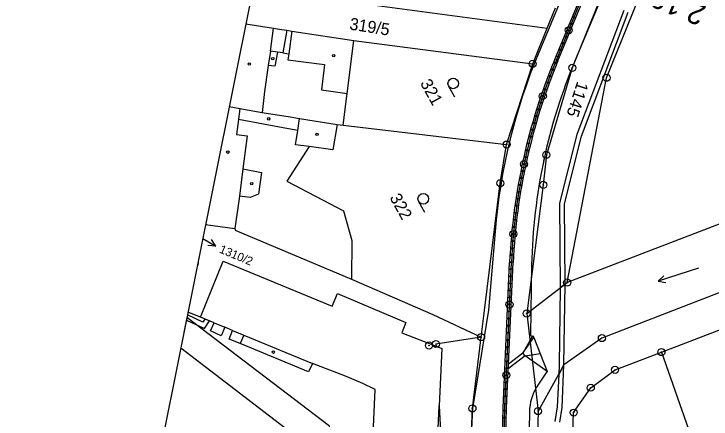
# Model space of a CAD drawing. Extents: x -548552 to -543113, y -1131925 to -1123599.
# Drawn here: x -548071.3 to -547972.8, y -1129654 to -1129596.7 of the extents above; entities that cross this region are included whole.
import ezdxf

# ---------------------------------------------------------------- set-up
doc = ezdxf.new("R2010")
doc.units = 0
for name, color, linetype in [('Hranice parcel', 7, 'Continuous'), ('HRANY', 7, 'Continuous'), ('Parcelní čísla', 7, 'Continuous'), ('Pop  PČ popisy', 7, 'Continuous'), ('Profile', 7, 'Continuous'), ('PROFILY NÁVRH', 7, 'Continuous'), ('STANIČENÍ', 7, 'Continuous'), ('Vnitřní kresba', 7, 'Continuous'), ('Věcná břemena k části', 7, 'Continuous'), ('Značky bodu BP', 7, 'Continuous'), ('Značky budov', 7, 'Continuous'), ('Značky kultur', 7, 'Continuous')]:
    doc.layers.add(name, color=color, linetype=linetype)

msp = doc.modelspace()

# ---------------------------------------------------------------- linework, layer by layer
at = {"layer": 'Hranice parcel'}
for p, q in [((-548037.579, -1129593.153), (-547995.97, -1129598.702)), ((-547995.97, -1129598.702), (-547994.817, -1129595.855)), ((-547998.02, -1129603.764), (-547995.97, -1129598.702)), ((-548023.301, -1129600.485), (-547998.02, -1129603.764)), ((-548001.707, -1129615.191), (-547998.02, -1129603.764)), ((-548025.671, -1129612.347), (-548024.825, -1129612.449)), ((-548024.825, -1129612.449), (-548001.707, -1129615.191)), ((-547998.869, -1129639.088), (-547993.145, -1129634.708)), ((-547998.869, -1129639.088), (-547997.264, -1129652.895)), ((-547979.823, -1129644.548), (-547953.676, -1129719.362)), ((-548012.947, -1129688.529), (-548011.248, -1129652.162))]:
    msp.add_line(p, q, dxfattribs=at)
for points in [[(-547943.94, -1129449.598), (-547944.146, -1129450.509), (-547954.87, -1129503.19), (-547960.132, -1129522.674), (-547965.208, -1129537.16), (-547992.427, -1129604.341), (-547996.089, -1129616.635), (-547996.527, -1129620.893), (-547998.869, -1129639.088)], [(-547993.145, -1129634.708), (-547987.59, -1129605.739), (-547960.434, -1129538.672), (-547955.317, -1129523.992), (-547949.866, -1129504.003), (-547942.366, -1129467.124)], [(-548038.577, -1129598.13), (-548034.635, -1129598.737), (-548033.531, -1129598.913), (-548032.796, -1129599.02), (-548032.057, -1129599.136), (-548023.301, -1129600.485)], [(-547897.642, -1129598.01), (-547902.313, -1129599.815), (-547935.147, -1129612.431), (-547948.722, -1129617.647), (-547993.145, -1129634.708)], [(-548024.825, -1129612.449), (-548024.231, -1129607.956), (-548023.301, -1129600.485)], [(-547888.295, -1129603.978), (-547898.682, -1129608.002), (-547945.124, -1129625.898), (-547988.244, -1129642.567), (-547993.598, -1129646.375), (-547997.264, -1129652.895)], [(-548040.919, -1129609.815), (-548039.435, -1129610.073), (-548036.242, -1129610.633), (-548032.28, -1129611.258), (-548030.977, -1129611.484), (-548025.671, -1129612.347)], [(-547979.823, -1129644.548), (-547943.108, -1129630.475), (-547896.786, -1129612.714), (-547895.105, -1129612.055)], [(-548025.671, -1129612.347), (-548026.277, -1129615.932), (-548029.609, -1129615.471), (-548032.764, -1129620.357), (-548024.77, -1129624.577), (-548023.568, -1129628.76), (-548023.654, -1129634.229)], [(-548005.313, -1129642.437), (-548004.835, -1129638.683), (-548002.599, -1129620.65), (-548001.707, -1129615.191)], [(-548044.262, -1129626.495), (-548040.119, -1129627.072), (-548040.087, -1129627.295), (-548023.654, -1129634.229)], [(-548045.235, -1129631.346), (-548045.372, -1129632.3), (-548045.424, -1129632.292)], [(-548023.654, -1129634.229), (-548012.121, -1129639.24), (-548005.313, -1129642.437)], [(-548020.334, -1129688.513), (-548021.556, -1129678.36), (-548020.302, -1129649.823), (-548022.053, -1129648.976), (-548024.478, -1129647.967), (-548029.122, -1129646.176), (-548029.703, -1129647.333), (-548039.361, -1129643.351), (-548040.933, -1129642.703), (-548040.434, -1129641.5), (-548041.546, -1129641.042), (-548042.036, -1129642.24), (-548043.561, -1129641.554), (-548043.064, -1129640.409), (-548044.987, -1129639.624), (-548046.749, -1129638.9)], [(-548019.133, -1129730.431), (-548011.696, -1129717.437), (-548008.935, -1129707.702), (-548006.542, -1129652.522), (-548005.313, -1129642.437)], [(-548005.313, -1129642.437), (-548011.703, -1129643.412), (-548011.685, -1129643.734), (-548010.865, -1129644.056), (-548011.248, -1129652.162)], [(-547994.011, -1129717.728), (-547992.884, -1129672.298), (-547992.237, -1129653.112), (-547989.811, -1129649.591), (-547986.388, -1129647.062), (-547979.823, -1129644.548)], [(-548011.248, -1129652.162), (-548009.853, -1129678.301), (-548009.88, -1129688.553), (-548012.947, -1129688.529)], [(-547997.264, -1129652.895), (-547997.82, -1129672.225), (-548001.102, -1129719.069), (-548002.902, -1129722.665), (-548006.626, -1129729.286)]]:
    msp.add_lwpolyline(points, dxfattribs=at)
at = {"layer": 'HRANY'}
msp.add_line((-547998.054, -1129642.265), (-547997.84, -1129642.499), dxfattribs=at)
at = {"layer": 'Pop  PČ popisy'}
for p, q in [((-548044.661, -1129628.487), (-548042.821, -1129629.547)), ((-548042.821, -1129629.547), (-548043.439, -1129628.614)), ((-548042.821, -1129629.547), (-548043.938, -1129629.482))]:
    msp.add_line(p, q, dxfattribs=at)
at = {"layer": 'Profile'}
for p, q in [((-548006.813, -1129439.666), (-548048.236, -1129646.318)), ((-548025.127, -1129531.035), (-548048.236, -1129646.318)), ((-548048.236, -1129646.318), (-548071.344, -1129761.602)), ((-548048.236, -1129646.318), (-548071.344, -1129761.602))]:
    msp.add_line(p, q, dxfattribs=at)
at = {"layer": 'PROFILY NÁVRH'}
for p, q in [((-547986.028, -1129575.53), (-547997.159, -1129602.147)), ((-547994.909, -1129603.145), (-547984.09, -1129576.932)), ((-547994.447, -1129603.336), (-547983.628, -1129577.123)), ((-547981.182, -1129577.47), (-547992.009, -1129603.233)), ((-548003.347, -1129627.479), (-548004.275, -1129638.622)), ((-548002.218, -1129652.424), (-548001.283, -1129631.859)), ((-548001.719, -1129652.447), (-548000.784, -1129631.882)), ((-547998.176, -1129632.222), (-547998.319, -1129642.096)), ((-548004.275, -1129638.622), (-548006.542, -1129652.522)), ((-547998.054, -1129642.265), (-547999.399, -1129644.68)), ((-547999.399, -1129644.68), (-547997.84, -1129642.499)), ((-547997.84, -1129642.499), (-547995.955, -1129647.282)), ((-547999.399, -1129644.68), (-548001.438, -1129646.275)), ((-547999.091, -1129645.074), (-547999.399, -1129644.68)), ((-547999.091, -1129645.074), (-547996.961, -1129644.73)), ((-547999.091, -1129645.074), (-548001.468, -1129646.933)), ((-547995.955, -1129647.282), (-547999.091, -1129645.074)), ((-548006.542, -1129652.522), (-548007.989, -1129685.887)), ((-548002.94, -1129686.397), (-548002.218, -1129652.43)), ((-548002.44, -1129686.407), (-548001.718, -1129652.441)), ((-547998.484, -1129653.519), (-547999.352, -1129686.07)), ((-547998.476, -1129652.972), (-547998.484, -1129653.519))]:
    msp.add_line(p, q, dxfattribs=at)
for centre, radius, start, end in [((-547919.998, -1129634.416), 83.637, 157.30515, 175.242), ((-547919.013, -1129633.909), 79.18, 157.2059, 178.7795), ((-547998.135, -1129642.099), 0.185, 179.17207, 295.86308), ((-547974.074, -1129663.851), 27.447, 142.86479, 148.4609), ((-547991.639, -1129653.071), 6.838, 148.4609, 179.17207)]:
    msp.add_arc(centre, radius, start, end, dxfattribs=at)
for major_axis, ratio in [((-22.444, -82.346), 0.999015), ((-22.313, -81.863), 0.999009)]:
    msp.add_ellipse((-547916.1, -1129635.695), major_axis=major_axis, ratio=ratio, start_param=4.586928, end_param=4.933273, dxfattribs=at)
at = {"layer": 'STANIČENÍ'}
for p, q in [((-547994.678, -1129603.241), (-547983.859, -1129577.028)), ((-548001.968, -1129652.436), (-548001.033, -1129631.87)), ((-548002.69, -1129686.402), (-548001.968, -1129652.436))]:
    msp.add_line(p, q, dxfattribs=at)
for centre, radius in [((-547992.174, -1129597.173), 0.1), ((-547992.556, -1129598.098), 0.1), ((-547992.937, -1129599.022), 0.5), ((-547992.937, -1129599.022), 0.1), ((-547993.319, -1129599.947), 0.1), ((-547993.7, -1129600.871), 0.1), ((-547994.082, -1129601.795), 0.1), ((-547994.463, -1129602.72), 0.1), ((-547994.844, -1129603.644), 0.1), ((-547995.215, -1129604.573), 0.1), ((-547995.925, -1129606.443), 0.1), ((-547995.576, -1129605.506), 0.1), ((-547996.263, -1129607.384), 0.1), ((-547996.591, -1129608.328), 0.5), ((-547996.591, -1129608.328), 0.1), ((-547996.907, -1129609.277), 0.1), ((-547997.212, -1129610.229), 0.1), ((-547997.506, -1129611.185), 0.1), ((-547997.788, -1129612.145), 0.1), ((-547998.06, -1129613.107), 0.1), ((-547998.32, -1129614.073), 0.1), ((-547998.569, -1129615.041), 0.1), ((-547998.806, -1129616.013), 0.1), ((-547999.032, -1129616.987), 0.1), ((-547999.246, -1129617.964), 0.5), ((-547999.246, -1129617.964), 0.1), ((-547999.449, -1129618.943), 0.1), ((-547999.64, -1129619.924), 0.1), ((-547999.82, -1129620.908), 0.1), ((-547999.989, -1129621.894), 0.1), ((-548000.145, -1129622.881), 0.1), ((-548000.291, -1129623.871), 0.1), ((-548000.424, -1129624.862), 0.1), ((-548000.546, -1129625.854), 0.1), ((-548000.656, -1129626.848), 0.1), ((-548000.755, -1129627.843), 0.5), ((-548000.755, -1129627.843), 0.1), ((-548000.841, -1129628.839), 0.1), ((-548000.917, -1129629.836), 0.1), ((-548000.98, -1129630.834), 0.1), ((-548001.032, -1129631.833), 0.1), ((-548001.077, -1129632.832), 0.1), ((-548001.123, -1129633.831), 0.1), ((-548001.168, -1129634.83), 0.1), ((-548001.213, -1129635.829), 0.1), ((-548001.259, -1129636.828), 0.1), ((-548001.304, -1129637.827), 0.5), ((-548001.304, -1129637.827), 0.1), ((-548001.35, -1129638.825), 0.1), ((-548001.395, -1129639.824), 0.1), ((-548001.44, -1129640.823), 0.1), ((-548001.486, -1129641.822), 0.1), ((-548001.531, -1129642.821), 0.1), ((-548001.577, -1129643.82), 0.1), ((-548001.622, -1129644.819), 0.1), ((-548001.667, -1129645.818), 0.1), ((-548001.713, -1129646.817), 0.1), ((-548001.758, -1129647.816), 0.5), ((-548001.758, -1129647.816), 0.1), ((-548001.804, -1129648.815), 0.1), ((-548001.849, -1129649.814), 0.1), ((-548001.894, -1129650.813), 0.1), ((-548001.94, -1129651.812), 0.1), ((-548001.976, -1129652.811), 0.1), ((-548001.997, -1129653.811), 0.1)]:
    msp.add_circle(centre, radius, dxfattribs=at)
for major_axis, ratio, start_param, end_param in [((-22.378, -82.104), 0.999012, 4.586928, 4.933273), ((-23.091, -84.719), 0.999042, 4.742803, 4.755033), ((-21.695, -79.596), 0.99898, 4.743539, 4.756619)]:
    msp.add_ellipse((-547916.1, -1129635.695), major_axis=major_axis, ratio=ratio, start_param=start_param, end_param=end_param, dxfattribs=at)
at = {"layer": 'Vnitřní kresba'}
for p, q in [((-548035.099, -1129601.98), (-548034.635, -1129598.737)), ((-548032.796, -1129599.02), (-548033.36, -1129602.227)), ((-548032.057, -1129599.136), (-548032.513, -1129602.352)), ((-548035.099, -1129601.98), (-548035.393, -1129603.985)), ((-548034.103, -1129602.125), (-548035.099, -1129601.98)), ((-548034.103, -1129602.125), (-548034.46, -1129604.119)), ((-548033.36, -1129602.227), (-548034.103, -1129602.125)), ((-548033.36, -1129602.227), (-548032.513, -1129602.352)), ((-548032.513, -1129602.352), (-548032.634, -1129603.185)), ((-548032.634, -1129603.185), (-548027.429, -1129603.886)), ((-548035.393, -1129603.985), (-548035.917, -1129607.696)), ((-548034.46, -1129604.119), (-548035.393, -1129603.985)), ((-548027.429, -1129603.886), (-548027.871, -1129607.437)), ((-548035.917, -1129607.696), (-548036.242, -1129610.633)), ((-548027.871, -1129607.437), (-548024.231, -1129607.956)), ((-548039.435, -1129610.073), (-548039.613, -1129611.647)), ((-548039.613, -1129611.647), (-548039.884, -1129613.776)), ((-548032.537, -1129612.979), (-548039.613, -1129611.647)), ((-548031.237, -1129613.219), (-548030.977, -1129611.484)), ((-548031.237, -1129613.219), (-548032.537, -1129612.979)), ((-548031.536, -1129615.215), (-548031.237, -1129613.219)), ((-548039.884, -1129613.776), (-548038.394, -1129613.967)), ((-548038.394, -1129613.967), (-548038.981, -1129618.616)), ((-548029.609, -1129615.471), (-548031.536, -1129615.215)), ((-548038.981, -1129618.616), (-548039.471, -1129622.492)), ((-548038.981, -1129618.616), (-548036.335, -1129619.138)), ((-548036.335, -1129619.138), (-548036.78, -1129622.187)), ((-548039.471, -1129622.492), (-548040.119, -1129627.072)), ((-548037.977, -1129622.669), (-548039.471, -1129622.492)), ((-548036.78, -1129622.187), (-548037.977, -1129622.669)), ((-548044.987, -1129639.624), (-548041.764, -1129631.669)), ((-548041.764, -1129631.669), (-548026.348, -1129638.07)), ((-548043.064, -1129640.409), (-548041.546, -1129641.042)), ((-548040.434, -1129641.5), (-548038.862, -1129642.148)), ((-548038.862, -1129642.148), (-548039.361, -1129643.351)), ((-548038.862, -1129642.148), (-548029.122, -1129646.176))]:
    msp.add_line(p, q, dxfattribs=at)
msp.add_lwpolyline([(-548026.348, -1129638.07), (-548025.615, -1129636.279), (-548015.948, -1129640.382), (-548016.521, -1129641.821), (-548011.685, -1129643.734)], dxfattribs=at)
at = {"layer": 'Věcná břemena k části'}
for p, q in [((-548046.9, -1129639.653), (-548047.762, -1129643.955)), ((-548046.825, -1129639.281), (-548046.975, -1129640.028))]:
    msp.add_line(p, q, dxfattribs=at)
for points in [[(-547985.164, -1129596.225), (-547991.786, -1129613.776), (-547994.253, -1129623.485), (-547994.133, -1129635.463), (-547993.435, -1129634.927), (-547993.542, -1129623.571), (-547991.123, -1129613.981), (-547984.517, -1129596.483)], [(-548047.762, -1129643.955), (-548030.392, -1129657.278), (-548020.263, -1129708.662), (-548010.216, -1129712.234), (-548009.12, -1129708.377), (-548016.785, -1129705.656), (-548020.159, -1129688.519), (-548020.334, -1129688.513), (-548020.594, -1129686.313), (-548026.764, -1129655.035), (-548046.9, -1129639.653)], [(-548046.975, -1129640.028), (-548044.39, -1129641.214), (-548043.689, -1129640.15), (-548044.349, -1129639.888), (-548044.635, -1129640.321), (-548046.825, -1129639.281)], [(-547994.184, -1129654.445), (-547993.853, -1129652.385), (-547993.598, -1129646.375), (-547994.35, -1129647.719), (-547994.554, -1129652.317), (-547994.877, -1129654.372)]]:
    msp.add_lwpolyline(points, dxfattribs=at)
msp.add_lwpolyline([(-547994.35, -1129647.719), (-547993.598, -1129646.375), (-547993.435, -1129634.927), (-547994.133, -1129635.463), (-547994.293, -1129646.361)], close=True, dxfattribs=at)
at = {"layer": 'Značky bodu BP'}
for centre, radius in [((-547998.02, -1129603.764), 0.5), ((-547998.02, -1129603.764), 0.0303), ((-547992.427, -1129604.341), 0.5), ((-547992.427, -1129604.341), 0.0303), ((-547987.59, -1129605.739), 0.5), ((-547987.59, -1129605.739), 0.0303), ((-548001.707, -1129615.191), 0.5), ((-548001.707, -1129615.191), 0.0303), ((-547996.089, -1129616.635), 0.5), ((-547996.089, -1129616.635), 0.0303), ((-548002.598, -1129620.65), 0.5), ((-548002.598, -1129620.65), 0.0303), ((-547996.527, -1129620.893), 0.5), ((-547996.527, -1129620.893), 0.0303), ((-547993.145, -1129634.708), 0.5), ((-547993.145, -1129634.708), 0.0303), ((-547998.869, -1129639.088), 0.5), ((-547998.869, -1129639.088), 0.0303), ((-548005.313, -1129642.437), 0.5), ((-548005.313, -1129642.437), 0.0303), ((-547988.243, -1129642.567), 0.5), ((-547988.243, -1129642.567), 0.0303), ((-548012.674, -1129643.62), 0.5), ((-548012.674, -1129643.62), 0.0303), ((-548011.703, -1129643.412), 0.5), ((-548011.703, -1129643.412), 0.0303), ((-547979.823, -1129644.548), 0.5), ((-547979.823, -1129644.548), 0.0303), ((-547986.388, -1129647.062), 0.5), ((-547986.388, -1129647.062), 0.0303), ((-547989.811, -1129649.591), 0.5), ((-547989.811, -1129649.591), 0.0303), ((-548006.542, -1129652.522), 0.5), ((-548006.542, -1129652.522), 0.0303), ((-547997.264, -1129652.895), 0.5), ((-547992.237, -1129653.111), 0.5), ((-547997.264, -1129652.895), 0.0303), ((-547992.237, -1129653.111), 0.0303)]:
    msp.add_circle(centre, radius, dxfattribs=at)
at = {"layer": 'Značky budov'}
for centre in [(-548034.76, -1129603.042), (-548026.147, -1129602.629), (-548038.075, -1129603.808), (-548035.332, -1129611.55), (-548028.5, -1129613.738), (-548041.113, -1129616.258), (-548037.733, -1129620.718), (-548034.678, -1129644.552)]:
    msp.add_circle(centre, 0.175, dxfattribs=at)
at = {"layer": 'Značky kultur'}
for p, q in [((-548009.909, -1129606.908), (-548009.06, -1129608.438)), ((-548014.144, -1129623.237), (-548013.295, -1129624.767)), ((-547974.573, -1129632.66), (-547980.278, -1129634.519)), ((-547980.278, -1129634.519), (-547979.504, -1129633.739)), ((-547980.278, -1129634.519), (-547979.194, -1129634.693))]:
    msp.add_line(p, q, dxfattribs=at)
for centre in [(-548009.253, -1129606.544), (-548013.488, -1129622.873)]:
    msp.add_circle(centre, 0.75, dxfattribs=at)

# ---------------------------------------------------------------- texts
at = {"layer": 'Parcelní čísla'}
for s, height, rotation, p in [('319/5', 1.7, 351.04291, (-548023.998, -1129598.904)), ('321', 1.7, 299.04291, (-548013.979, -1129606.5)), ('1145', 1.7, 252.04291, (-547991.705, -1129606.148)), ('322', 1.7, 299.04291, (-548018.296, -1129622.681)), ('1310/2', 1.2, 337.04291, (-548042.413, -1129630.433))]:
    msp.add_text(s, height=height, rotation=rotation, dxfattribs=at).set_placement(p)
at = {"layer": 'STANIČENÍ'}
msp.add_text('2,100', height=3, rotation=157.57242, dxfattribs=at).set_placement((-547973.326, -1129595.712))

doc.saveas('drawing.dxf')
